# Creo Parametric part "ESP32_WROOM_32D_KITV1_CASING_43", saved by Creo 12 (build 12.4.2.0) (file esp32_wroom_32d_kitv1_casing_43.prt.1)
Units: Custom; MM, KILOGRAM, SECS

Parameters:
  PTC_WM_ITERATION = "0"
  PTC_WM_VERSION = "-.0"
  PTC_WM_LIFECYCLE_STATE = "In Work"
  PTC_WM_LIFECYCLE = "MO_CADDocument"
  PTC_WM_CREATED_BY = "Maximilian Roepper (Z0017RMS: MO)"
  PTC_WM_CREATED_ON = "18-Sep-26 11:36:42 AM"
  PTC_WM_MODIFIED_BY = "Maximilian Roepper (Z0017RMS: MO)"
  PTC_WM_MODIFIED_ON = "18-Sep-26 11:36:46 AM"
  PDMLINKNUMBER = "PDM000071454850"
  PTC_WM_NAME = "esp32_wroom_32d_kitv1_casing_43.prt"
  PTC_WM_NUMBER = "PDM000071454850"

Other parameters: WEIGHT, WEIGHT_FACTOR, WEIGHT_ADD, _MASS_TEMP, _DIFF_TEMP, MC_ERRORS, SUPPLIER

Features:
  1. coordinate system
  2. datum plane "PRT_YZ"
  3. datum plane "PRT_XY"
  4. datum plane "PRT_XZ"
  5. coordinate system
  6. datum axis
  7. datum axis
  8. datum axis
  9. coordinate system
  10. imported feature
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
Other named items: PRT, SIEMENS_MO, DRW_VIEW_ORG, PRT_X, PRT_Y, PRT_Z, CS0, ROUGH_GROB

Layers: 00_STD_CSYS-KSYS, 01_STD_PLANES-EBENEN, 02_STD_AXES-ACHSEN, 03_STD_CSYS-KSYS, 24_IMPORT_FEAT-IMPORT_KE

Surfaces: 103 plane, 51 cylinder, 2 cone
